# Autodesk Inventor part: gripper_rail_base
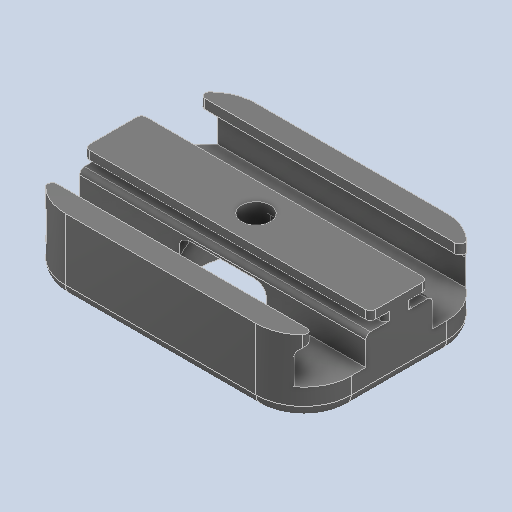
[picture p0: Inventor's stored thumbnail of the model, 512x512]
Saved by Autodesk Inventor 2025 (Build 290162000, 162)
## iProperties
Created: 2025-06
Part Number: gripper_rail_base
Material: Plastica ABS
Document SubType Name: Modeling
Designer: Ryzen5700u
Density: 1.06 g/cm^3
Appearance: Default
Author: Ryzen5700u
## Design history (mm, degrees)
feature "Solido1"
node "Solido2"
